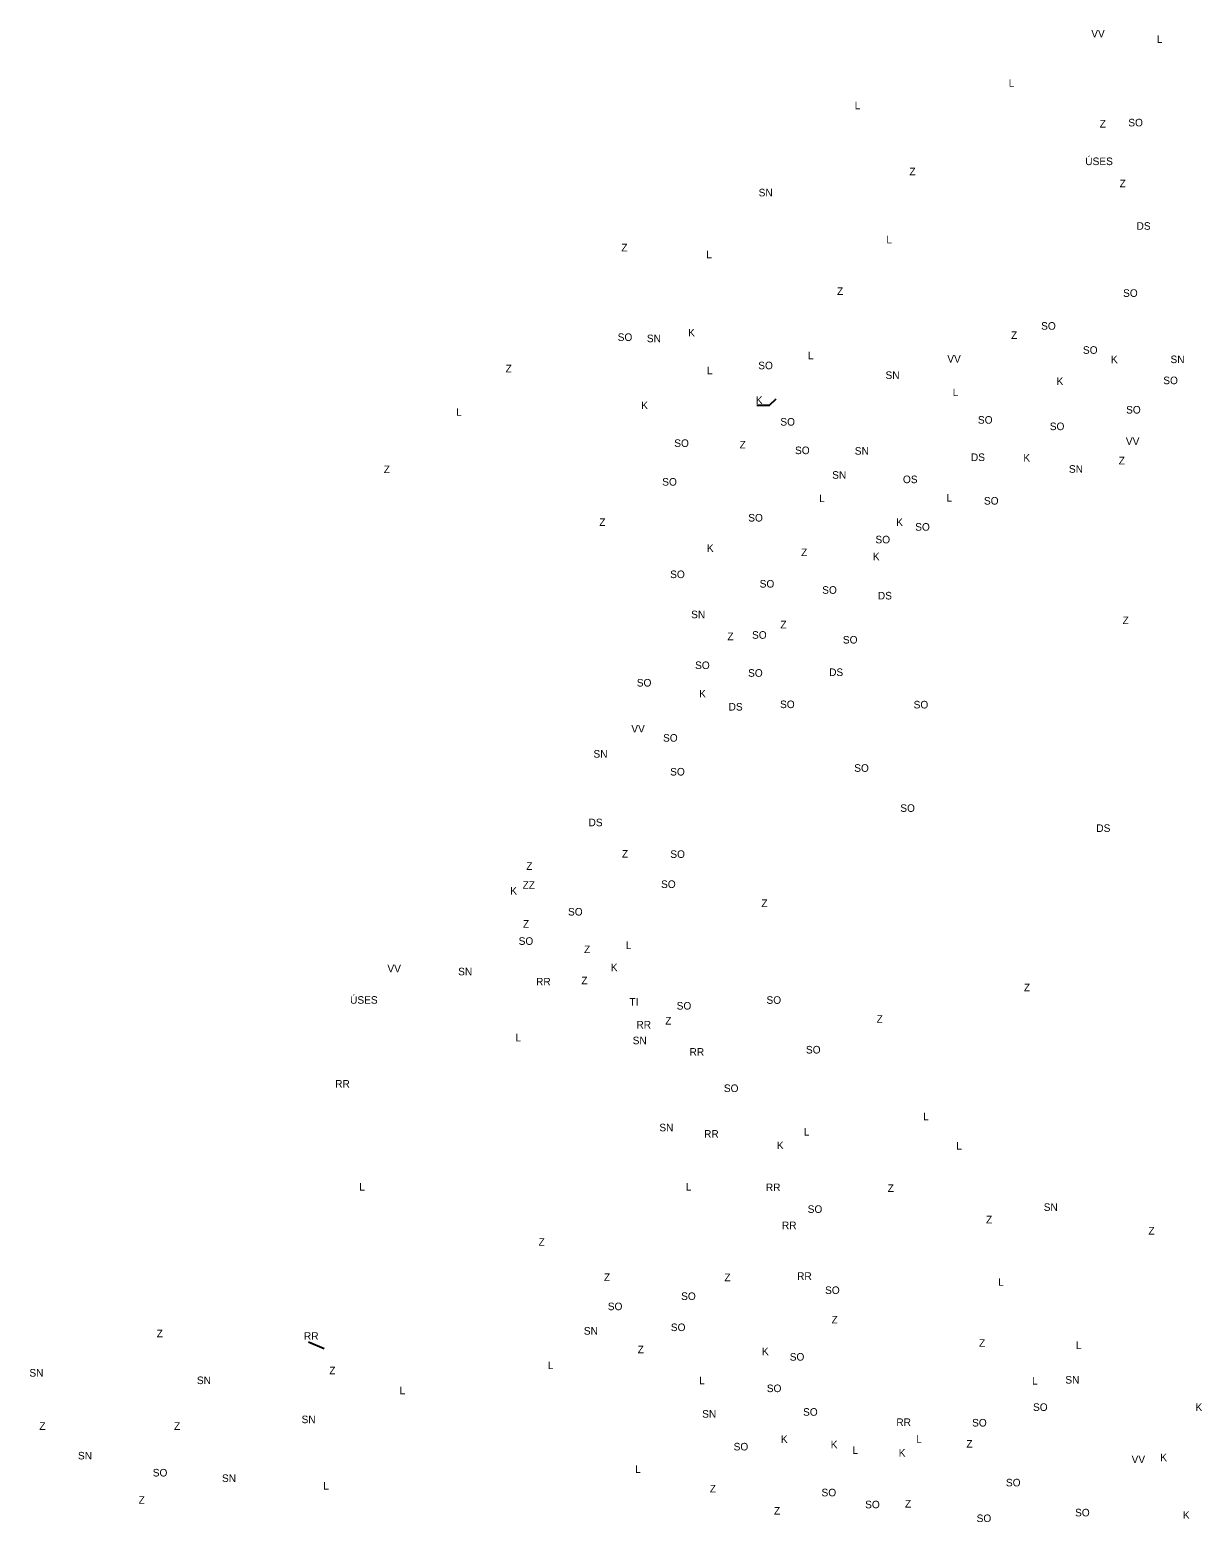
# Model space of a CAD drawing. Extents: x -445021 to -436233, y -1141846 to -1129798.
# Drawn here: x -443696 to -442148, y -1132159 to -1130188 of the extents above; entities that cross this region are included whole.
import ezdxf

# ---------------------------------------------------------------- set-up
doc = ezdxf.new("R2010")
doc.units = 0
doc.layers.add('Vrstva 4', color=7, linetype='Continuous')

msp = doc.modelspace()

# ---------------------------------------------------------------- linework, layer by layer
at = {"layer": 'Vrstva 4'}
msp.add_line((-443328.2, -1131920.4), (-443307.7, -1131929.4), dxfattribs=at)
msp.add_lwpolyline([(-442736, -1130683.7), (-442719.4, -1130683.7), (-442710.7, -1130675.1)], dxfattribs=at)

# ---------------------------------------------------------------- texts
for s, p in [('VV', (-442294.5, -1130197.9)), ('L', (-442208, -1130205.1)), ('L', (-442403.5, -1130263.1)), ('L', (-442606.9, -1130292.7)), ('Z', (-442283.4, -1130316.9)), ('SO', (-442245.6, -1130315.4)), ('Z', (-442534.6, -1130380)), ('ÚSES', (-442302.4, -1130366.5)), ('Z', (-442257.1, -1130395.8)), ('SN', (-442733.8, -1130407.8)), ('DS', (-442234.7, -1130451.9)), ('Z', (-442915.1, -1130480.4)), ('L', (-442565.1, -1130469.9)), ('L', (-442803, -1130489.6)), ('Z', (-442630.2, -1130538)), ('SO', (-442252.5, -1130540.5)), ('SO', (-442919.9, -1130598.7)), ('K', (-442826.9, -1130592.8)), ('Z', (-442400.4, -1130596.1)), ('SO', (-442360.7, -1130583.9)), ('SN', (-442881.4, -1130600.4)), ('SO', (-442305.5, -1130615.7)), ('SO', (-442734.3, -1130636.1)), ('L', (-442668.7, -1130623)), ('VV', (-442484.6, -1130627.4)), ('K', (-442268.5, -1130628.1)), ('SN', (-442189.9, -1130628)), ('Z', (-443067.9, -1130640.2)), ('L', (-442802, -1130642.8)), ('SN', (-442566.2, -1130648.9)), ('K', (-442340.3, -1130656.9)), ('SO', (-442199.4, -1130655.8)), ('L', (-442477.5, -1130671.6)), ('L', (-443133.2, -1130697.6)), ('K', (-442888.8, -1130688.8)), ('K', (-442737.6, -1130681.9)), ('SO', (-442248.5, -1130694.6)), ('SO', (-442705.1, -1130710.5)), ('SO', (-442444.2, -1130708)), ('SO', (-442349.3, -1130716.5)), ('VV', (-442248.8, -1130736.2)), ('SO', (-442845.2, -1130738.7)), ('Z', (-442758.9, -1130740.7)), ('SO', (-442685.7, -1130748.2)), ('SN', (-442606.8, -1130748.9)), ('Z', (-443228.8, -1130773.3)), ('DS', (-442453.4, -1130757.3)), ('K', (-442384.2, -1130758.1)), ('SN', (-442324, -1130772.8)), ('Z', (-442258.2, -1130761.7)), ('SO', (-442861.1, -1130789.8)), ('SN', (-442636.6, -1130780.7)), ('OS', (-442543.2, -1130786.5)), ('L', (-442653.9, -1130811.6)), ('L', (-442485.7, -1130810.8)), ('SO', (-442436.2, -1130814.8)), ('Z', (-442944.2, -1130843)), ('SO', (-442747.5, -1130837.2)), ('K', (-442552.1, -1130843.1)), ('SO', (-442527, -1130849.3)), ('SO', (-442579.5, -1130866)), ('K', (-442802.1, -1130877.3)), ('Z', (-442677.7, -1130882.9)), ('K', (-442583, -1130888.4)), ('SO', (-442850.6, -1130911.9)), ('SO', (-442732.4, -1130924.4)), ('SO', (-442649.8, -1130932.6)), ('DS', (-442576.3, -1130940.1)), ('SN', (-442822.9, -1130964.9)), ('Z', (-442253.2, -1130972.7)), ('SO', (-442742.5, -1130992)), ('Z', (-442705, -1130978.3)), ('Z', (-442775, -1130993.9)), ('SO', (-442622.5, -1130998.3)), ('SO', (-442817.7, -1131032)), ('SO', (-442747.7, -1131042.2)), ('DS', (-442640.7, -1131041.2)), ('SO', (-442894.7, -1131055.1)), ('K', (-442812.3, -1131069.5)), ('DS', (-442773.4, -1131086.8)), ('SO', (-442705.5, -1131083.6)), ('SO', (-442529.1, -1131084)), ('VV', (-442901.9, -1131115.8)), ('SO', (-442860, -1131127.9)), ('SN', (-442951.9, -1131149)), ('SO', (-442607.5, -1131167.7)), ('SO', (-442850.6, -1131172.6)), ('SO', (-442546.7, -1131220.6)), ('DS', (-442958.4, -1131239.6)), ('DS', (-442287.8, -1131247.1)), ('Z', (-442914.3, -1131281)), ('SO', (-442850.4, -1131281.4)), ('Z', (-443040.7, -1131297.2)), ('ZZ', (-443045.5, -1131322.2)), ('SO', (-442862.6, -1131321.1)), ('K', (-443061.8, -1131329.9)), ('Z', (-442730.2, -1131346.3)), ('SO', (-442985.5, -1131357.5)), ('Z', (-443045, -1131373.6)), ('SO', (-443050.7, -1131396.2)), ('Z', (-442964.3, -1131407.1)), ('L', (-442909.1, -1131401.8)), ('VV', (-443224, -1131432.6)), ('SN', (-443130.6, -1131436.5)), ('K', (-442929, -1131431.1)), ('RR', (-443027.7, -1131449.8)), ('Z', (-442967.9, -1131448.3)), ('Z', (-442383.5, -1131457.5)), ('ÚSES', (-443273.3, -1131474)), ('TI', (-442904.3, -1131476.6)), ('SO', (-442842, -1131481.7)), ('SO', (-442723.4, -1131474.1)), ('Z', (-442857.1, -1131501.5)), ('Z', (-442578, -1131499.2)), ('L', (-443054.9, -1131523.7)), ('RR', (-442895.2, -1131506.7)), ('SN', (-442900.1, -1131527.5)), ('RR', (-442825, -1131542.6)), ('SO', (-442671.3, -1131539.7)), ('RR', (-443293, -1131584.8)), ('SO', (-442779.7, -1131590.6)), ('SN', (-442864.9, -1131642.5)), ('L', (-442516.5, -1131627.9)), ('RR', (-442805.8, -1131650.9)), ('L', (-442674.1, -1131648)), ('K', (-442709.6, -1131666)), ('L', (-442472.7, -1131666.6)), ('L', (-443261.1, -1131720.8)), ('L', (-442829.9, -1131720.8)), ('RR', (-442724.2, -1131721.5)), ('Z', (-442563.4, -1131722.6)), ('SO', (-442669, -1131750.2)), ('SN', (-442357.3, -1131747.6)), ('RR', (-442703, -1131771.7)), ('Z', (-442433.4, -1131764)), ('Z', (-442219, -1131778.8)), ('Z', (-443024.4, -1131793.6)), ('Z', (-442938.1, -1131840.2)), ('Z', (-442779, -1131840.4)), ('RR', (-442683, -1131838.7)), ('SO', (-442646, -1131857.3)), ('L', (-442417.5, -1131846.5)), ('SO', (-442933, -1131878.7)), ('SO', (-442836.1, -1131865.2)), ('Z', (-442637.5, -1131896.2)), ('Z', (-443528.7, -1131914.5)), ('RR', (-443334.2, -1131917.8)), ('SN', (-442964.6, -1131911)), ('SO', (-442849.7, -1131906.3)), ('Z', (-442893.5, -1131935.6)), ('K', (-442729.4, -1131938.1)), ('Z', (-442442.7, -1131927)), ('L', (-442314.7, -1131930)), ('L', (-443012.2, -1131956.5)), ('SO', (-442692.7, -1131945.3)), ('SN', (-443696.8, -1131966.4)), ('SN', (-443475.6, -1131976.3)), ('Z', (-443300.8, -1131963.4)), ('L', (-442812.3, -1131976.6)), ('L', (-442372.7, -1131976.9)), ('SN', (-442328.7, -1131975.6)), ('L', (-443207.9, -1131989.8)), ('SO', (-442723, -1131986.9)), ('SO', (-442675.1, -1132018.1)), ('SO', (-442371.4, -1132011.7)), ('K', (-442156.8, -1132011.8)), ('Z', (-443683.7, -1132036.7)), ('Z', (-443505.8, -1132036.7)), ('SN', (-443337.4, -1132027.9)), ('SN', (-442808.3, -1132020.7)), ('RR', (-442551.9, -1132031.6)), ('SO', (-442451.9, -1132032.3)), ('K', (-442704.4, -1132054)), ('L', (-442525.9, -1132053.7)), ('SN', (-443632.7, -1132075.8)), ('SO', (-442766.8, -1132063.9)), ('K', (-442638.6, -1132061.1)), ('L', (-442609.9, -1132068.5)), ('K', (-442548.8, -1132072.1)), ('Z', (-442459.4, -1132060.2)), ('L', (-442896.8, -1132093.7)), ('VV', (-442241.2, -1132080.6)), ('K', (-442203.4, -1132078.1)), ('SO', (-443533.9, -1132098.3)), ('SN', (-443442.5, -1132105.6)), ('L', (-443308.7, -1132115.6)), ('SO', (-442407.2, -1132111.4)), ('Z', (-443552.6, -1132134.4)), ('Z', (-442798.2, -1132119.4)), ('SO', (-442650.7, -1132124.5)), ('Z', (-442713.5, -1132148.6)), ('SO', (-442593.1, -1132140.3)), ('Z', (-442540.5, -1132139.3)), ('SO', (-442315.9, -1132151)), ('K', (-442173.4, -1132154.2)), ('SO', (-442445.9, -1132158.5))]:
    msp.add_text(s, height=10, dxfattribs=at).set_placement(p)

doc.saveas('drawing.dxf')
